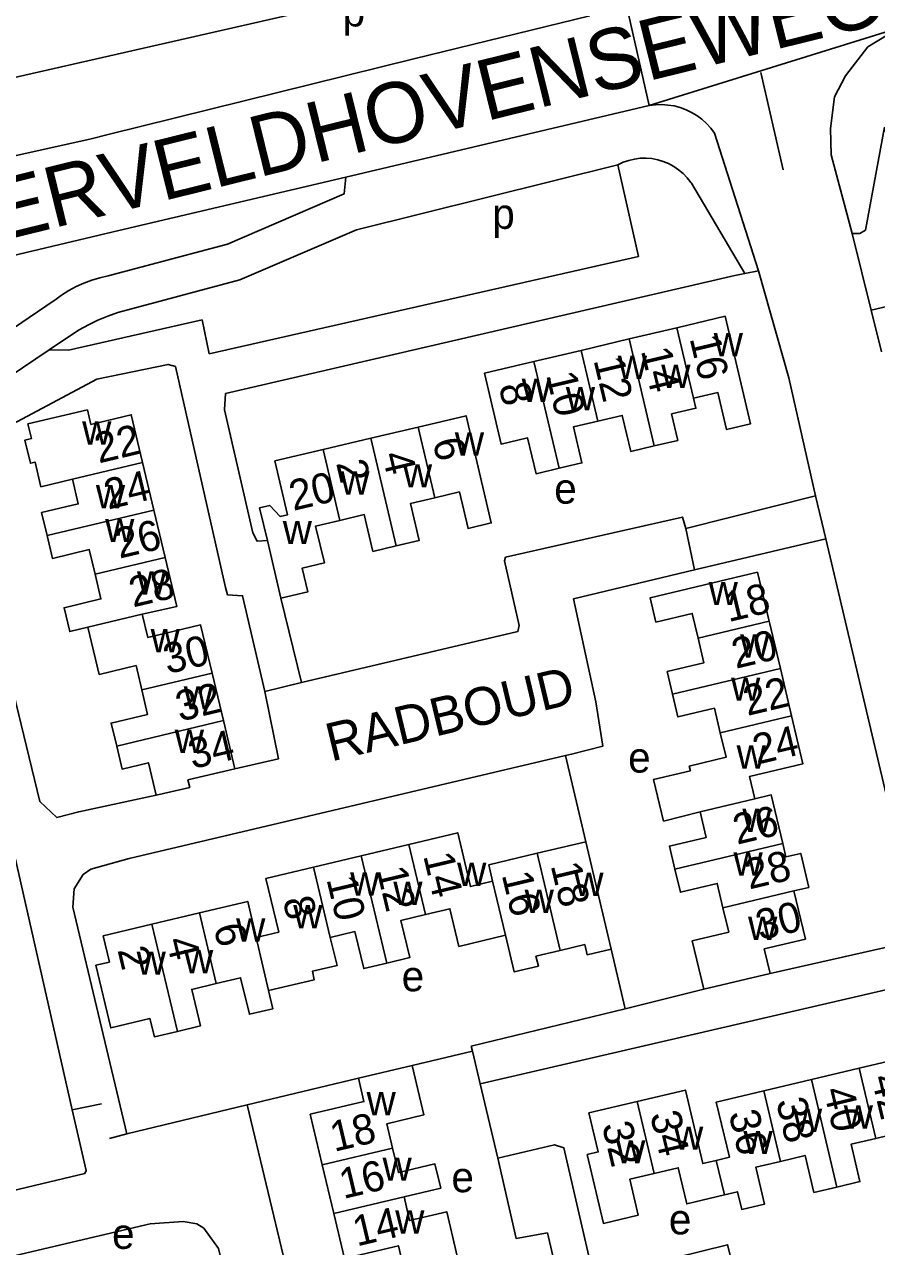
# Model space of a CAD drawing. Extents: x 157646 to 159241, y 379213 to 381217.
# Drawn here: x 158247.5 to 158360.1, y 380777.5 to 380938.8 of the extents above; entities that cross this region are included whole.
import ezdxf

# ---------------------------------------------------------------- set-up
doc = ezdxf.new("R2010")
doc.units = 0
for name, color, linetype in [('BLT_Basislijn', 7, 'Continuous'), ('BLT_Bebouwing', 7, 'Continuous'), ('BLT_Centroide', 7, 'Continuous'), ('BLT_Huisnummer', 7, 'Continuous'), ('BLT_Huisnummer_ tussenligend', 7, 'Continuous'), ('BLT_Onderverdeling_panden', 7, 'Continuous'), ('BLT_Straatnaam', 7, 'Continuous'), ('BLT_Straatnaam_hoofdweg', 7, 'Continuous'), ('BLT_Vlakafsluiter', 7, 'Continuous')]:
    doc.layers.add(name, color=color, linetype=linetype)

msp = doc.modelspace()

# ---------------------------------------------------------------- linework, layer by layer
at = {"layer": 'BLT_Basislijn'}
for p, q in [((158344.76, 380932.48), (158347.72, 380919.64)), ((158330.04, 380928.15), (158289.95, 380918.69)), ((158338.65, 380924.49), (158344.45, 380906.32)), ((158325.89, 380920.33), (158328.62, 380908.21)), ((158289.95, 380918.69), (158259.98, 380911.64)), ((158335.61, 380917.87), (158342.68, 380905.97)), ((158356.85, 380911.26), (158359.36, 380901.14)), ((158328.62, 380908.21), (158271.92, 380895.35)), ((158341.32, 380905.69), (158342.68, 380905.97)), ((158342.68, 380905.97), (158344.45, 380906.32)), ((158238.17, 380893.44), (158251.44, 380902.38)), ((158359.36, 380901.14), (158360.69, 380895.64)), ((158270.97, 380899.83), (158253.35, 380895.83)), ((158271.92, 380895.35), (158270.97, 380899.83)), ((158254.24, 380898.23), (158250.78, 380895.91)), ((158241.22, 380889.46), (158250.78, 380895.91)), ((158253.35, 380895.83), (158250.78, 380895.91)), ((158334.87, 380872.3), (158352, 380876.62)), ((158352, 380876.62), (158353.34, 380870.93)), ((158334.87, 380872.3), (158336.03, 380866.86)), ((158336.03, 380866.86), (158353.34, 380870.93)), ((158353.34, 380870.93), (158365.82, 380818.05)), ((158284.12, 380851.99), (158279.27, 380850.8)), ((158318.96, 380842.32), (158321.67, 380830.96)), ((158365.82, 380818.05), (158346.01, 380813.55)), ((158325.03, 380816.79), (158326.86, 380808.89)), ((158307.72, 380798.98), (158367.08, 380812.75)), ((158306.69, 380803.29), (158298.71, 380801.4)), ((158306.69, 380803.29), (158307.72, 380798.98)), ((158276.95, 380796.21), (158291.62, 380799.72)), ((158307.72, 380798.98), (158310.03, 380789.16)), ((158257.71, 380796.35), (158253.84, 380795.54)), ((158261.04, 380792.41), (158276.95, 380796.21)), ((158258.76, 380791.78), (158261.04, 380792.41)), ((158316.59, 380779.32), (158319.36, 380767.4))]:
    msp.add_line(p, q, dxfattribs=at)
for points in [[(158281.68, 380943.57), (158282.78, 380940.14), (158232.81, 380928.81), (158227.42, 380938.7), (158290.8, 380994.41), (158296.28, 380985.19)], [(158322.18, 380939.98), (158298.93, 380934.3), (158258.59, 380924.33)], [(158363.04, 380938.38), (158358.91, 380935.88), (158355.95, 380932.05), (158354.51, 380929.29), (158353.99, 380925.13), (158354.08, 380921.65), (158356.85, 380911.26)], [(158338.65, 380924.49), (158338.16, 380925.16), (158337.61, 380925.77), (158337, 380926.32), (158336.34, 380926.81), (158335.64, 380927.24), (158334.9, 380927.59), (158334.12, 380927.87), (158333.33, 380928.08), (158332.51, 380928.21), (158331.69, 380928.26), (158330.87, 380928.22), (158330.04, 380928.15)], [(158356.85, 380911.26), (158357.85, 380911.26), (158358.58, 380911.69), (158361.13, 380925.29)], [(158361.13, 380925.29), (158366.65, 380902.84), (158359.36, 380901.14)], [(158229.41, 380918.03), (158244.68, 380921.15), (158256.32, 380923.74), (158258.59, 380924.33)], [(158259.86, 380900.81), (158275.98, 380905.11), (158291.37, 380911.75), (158325.89, 380920.33)], [(158325.89, 380920.33), (158326.59, 380920.65), (158327.32, 380920.9), (158328.08, 380921.08), (158328.84, 380921.17), (158329.62, 380921.19), (158330.39, 380921.13), (158331.15, 380920.99), (158331.89, 380920.77), (158332.6, 380920.47), (158333.28, 380920.1), (158333.92, 380919.67), (158334.51, 380919.17), (158335.05, 380918.61), (158335.52, 380918), (158335.61, 380917.87)], [(158258.57, 380905.65), (158274.33, 380909.85), (158289.76, 380916.5), (158289.95, 380918.69)], [(158232.12, 380903.76), (158240.65, 380907.05), (158259.98, 380911.64)], [(158341.32, 380905.69), (158274.08, 380890.11), (158273.94, 380887.99), (158277.67, 380871.72), (158278.24, 380870.65), (158279.6, 380870.7)], [(158344.45, 380906.32), (158348.46, 380892.19), (158352, 380876.62)], [(158258.57, 380905.65), (158257.48, 380905.41), (158256.4, 380905.1), (158255.36, 380904.71), (158254.34, 380904.25), (158253.36, 380903.71), (158252.42, 380903.11), (158251.52, 380902.44), (158251.44, 380902.38)], [(158259.86, 380900.81), (158258.53, 380900.35), (158257.23, 380899.82), (158255.96, 380899.21), (158254.74, 380898.53), (158254.24, 380898.23)], [(158229.9, 380879.86), (158238.93, 380882.66), (158240.62, 380883.28), (158257.08, 380892.02), (158266.49, 380893.96), (158267.45, 380893.67), (158274.06, 380864.51), (158274.34, 380863.54), (158276.33, 380863.42), (158279.27, 380850.8)], [(158240.4, 380873.84), (158249.53, 380836.28), (158251.78, 380834.15), (158254.68, 380834.9), (158264.9, 380837.08)], [(158284.12, 380851.99), (158312.7, 380858.71), (158312.86, 380859.51), (158310.92, 380868.04), (158311.07, 380868.51), (158334.41, 380873.8), (158334.87, 380872.3)], [(158318.96, 380842.32), (158319.77, 380842.51), (158323.9, 380843.55), (158322.99, 380849.41), (158320.05, 380863.03), (158336.03, 380866.86)], [(158281.4, 380863.12), (158284.12, 380851.99)], [(158279.27, 380850.8), (158281.07, 380841.88), (158275.32, 380840.56)], [(158261.04, 380792.41), (158253.93, 380822.33), (158254.09, 380824.72), (158255.27, 380826.63), (158256.28, 380827.34), (158261.37, 380828.76), (158318.96, 380842.32)], [(158253.84, 380795.54), (158246.19, 380829.22), (158236.45, 380826.81)], [(158326.86, 380808.89), (158327.58, 380809.06), (158337.23, 380811.47)], [(158326.86, 380808.89), (158306.53, 380803.98), (158306.69, 380803.29)], [(158287.22, 380753.19), (158286.95, 380754.31), (158276.95, 380796.21)], [(158222.97, 380779.39), (158223.89, 380779.61), (158255.5, 380787.15), (158255.66, 380787.56), (158253.84, 380795.54)], [(158322.72, 380773.38), (158318.74, 380790.56), (158317.53, 380790.94), (158310.03, 380789.16)], [(158316.59, 380779.32), (158312.44, 380778.59), (158310.03, 380789.16)], [(158235.05, 380773.67), (158264.14, 380780.52), (158268.46, 380780.84), (158270.28, 380780.5), (158271.2, 380779.95), (158273.15, 380777.26), (158281.54, 380741.81)], [(158341.59, 380772.88), (158340.39, 380777.74), (158322.72, 380773.38)]]:
    msp.add_lwpolyline(points, dxfattribs=at)
at = {"layer": 'BLT_Bebouwing'}
for p, q in [((158333.68, 380898.81), (158327.37, 380897.32)), ((158327.37, 380897.32), (158321.04, 380895.82)), ((158321.04, 380895.82), (158314.79, 380894.34)), ((158299.53, 380885.7), (158293.25, 380884.22)), ((158293.25, 380884.22), (158286.98, 380882.73)), ((158264.61, 380874.73), (158263.12, 380881)), ((158266.1, 380868.46), (158264.61, 380874.73)), ((158345.87, 380860.06), (158347.36, 380853.81)), ((158273.8, 380846.94), (158272.31, 380853.2)), ((158347.36, 380853.81), (158348.84, 380847.57)), ((158275.32, 380840.56), (158273.8, 380846.94)), ((158298.27, 380830.59), (158292, 380829.1)), ((158321.67, 380830.96), (158315.24, 380829.43)), ((158325.03, 380816.79), (158321.67, 380830.96)), ((158292, 380829.1), (158285.7, 380827.61)), ((158270.62, 380821.55), (158264.36, 380820.06)), ((158346.01, 380813.55), (158337.23, 380811.47)), ((158298.71, 380801.4), (158291.62, 380799.72)), ((158357.77, 380801.05), (158351.47, 380799.55)), ((158351.47, 380799.55), (158345.17, 380798.06)), ((158286.85, 380788.3), (158288.38, 380781.86))]:
    msp.add_line(p, q, dxfattribs=at)
for points in [[(158335.89, 380889.49), (158339.1, 380890.25), (158340.26, 380885.36), (158343.41, 380886.11), (158340.05, 380900.32), (158333.68, 380898.81)], [(158314.79, 380894.34), (158308.27, 380892.8), (158310.48, 380883.44), (158313.97, 380884.26), (158315.09, 380879.53), (158318.12, 380880.25)], [(158263.12, 380881), (158261.62, 380887.31), (158256.3, 380886.04), (158255.84, 380887.95), (158247.97, 380886.12), (158248.43, 380884.17), (158247.58, 380883.97), (158248.3, 380880.91), (158248.92, 380881.06), (158249.69, 380877.81), (158253.85, 380878.8)], [(158330.7, 380883.2), (158333.8, 380883.93), (158332.98, 380887.42), (158336.2, 380888.18), (158335.89, 380889.49)], [(158301.74, 380876.37), (158304.96, 380877.13), (158306.11, 380872.3), (158309.18, 380873.03), (158305.84, 380887.19), (158299.53, 380885.7)], [(158318.12, 380880.25), (158321.15, 380880.96), (158320.03, 380885.71), (158323.25, 380886.47)], [(158323.25, 380886.47), (158326.48, 380887.23), (158327.6, 380882.47), (158330.7, 380883.2)], [(158286.98, 380882.73), (158280.59, 380881.22), (158282.27, 380874.12), (158281.29, 380873.89), (158279.92, 380875.35), (158278.57, 380875.04)], [(158253.85, 380878.8), (158254.62, 380875.55), (158249.79, 380874.4), (158250.5, 380871.38)], [(158278.57, 380875.04), (158279.6, 380870.7)], [(158296.61, 380870), (158299.67, 380870.73), (158298.51, 380875.61), (158301.74, 380876.37)], [(158289.19, 380873.38), (158292.4, 380874.14), (158293.55, 380869.28), (158296.61, 380870)], [(158281.4, 380863.12), (158284.95, 380863.96), (158284.21, 380867.07), (158287.13, 380867.76), (158285.98, 380872.62), (158289.19, 380873.38)], [(158250.5, 380871.38), (158251.22, 380868.36), (158256.08, 380869.51), (158256.85, 380866.26)], [(158279.6, 380870.7), (158281.4, 380863.12)], [(158263.07, 380860.98), (158267.64, 380861.99), (158266.1, 380868.46)], [(158256.85, 380866.26), (158257.62, 380863), (158252.75, 380861.84), (158253.5, 380858.7), (158255.91, 380859.28)], [(158336.48, 380857.83), (158335.71, 380861.09), (158330.92, 380859.95), (158330.16, 380863.17), (158344.33, 380866.53), (158345.87, 380860.06)], [(158272.31, 380853.2), (158270.79, 380859.58), (158263.8, 380857.92), (158263.07, 380860.98)], [(158255.91, 380859.28), (158257.39, 380853.05), (158262.26, 380854.2), (158263.03, 380850.99)], [(158333.12, 380850.42), (158332.41, 380853.42), (158337.25, 380854.57), (158336.48, 380857.83)], [(158263.03, 380850.99), (158263.79, 380847.77), (158258.97, 380846.62), (158259.7, 380843.59)], [(158339.42, 380845.34), (158338.65, 380848.57), (158333.83, 380847.42), (158333.12, 380850.42)], [(158348.84, 380847.57), (158350.34, 380841.25), (158343.28, 380839.57), (158343.98, 380836.63)], [(158336.76, 380834.92), (158331.93, 380833.68), (158330.62, 380839.18), (158335.48, 380840.33), (158335.33, 380840.95), (158340.19, 380842.1), (158339.42, 380845.34)], [(158259.7, 380843.59), (158260.42, 380840.55), (158263.89, 380841.38), (158264.9, 380837.08)], [(158264.9, 380837.08), (158269.35, 380838.13), (158269.11, 380839.14), (158275.32, 380840.56)], [(158343.98, 380836.63), (158346.14, 380837.14), (158347.66, 380830.72)], [(158333.43, 380827.34), (158332.71, 380830.38), (158337.57, 380831.53), (158336.76, 380834.92)], [(158309.35, 380825.74), (158306.43, 380825.04), (158304.74, 380832.13), (158298.27, 380830.59)], [(158347.66, 380830.72), (158348.08, 380828.95), (158350.05, 380829.42), (158351.11, 380824.93), (158349.15, 380824.47)], [(158315.24, 380829.43), (158308.86, 380827.91), (158309.35, 380825.74)], [(158285.7, 380827.61), (158279.42, 380826.11), (158281.1, 380819.02), (158278.12, 380818.31)], [(158339.77, 380822.24), (158339.01, 380825.45), (158334.15, 380824.29), (158333.43, 380827.34)], [(158349.15, 380824.47), (158350.66, 380818.1), (158345.23, 380816.8), (158346.01, 380813.55)], [(158278.12, 380818.31), (158277.01, 380823.07), (158270.62, 380821.55)], [(158300.47, 380821.33), (158303.71, 380822.1), (158304.89, 380817.14), (158311.05, 380818.6)], [(158337.23, 380811.47), (158335.71, 380817.88), (158340.54, 380819.03), (158339.77, 380822.24)], [(158295.37, 380814.93), (158298.41, 380815.65), (158297.24, 380820.56), (158300.47, 380821.33)], [(158264.36, 380820.06), (158257.93, 380818.53), (158258.75, 380815.07), (158256.95, 380814.64), (158258.91, 380806.38), (158264.1, 380807.61), (158264.68, 380805.2), (158267.72, 380805.92)], [(158287.91, 380818.33), (158291.16, 380819.1), (158292.33, 380814.21), (158295.37, 380814.93)], [(158311.05, 380818.6), (158312.2, 380813.76), (158315.39, 380814.52), (158315.08, 380815.84), (158318.29, 380816.6)], [(158279.76, 380811.3), (158285.8, 380812.74), (158285.56, 380813.85), (158288.8, 380814.6), (158287.91, 380818.33)], [(158318.29, 380816.6), (158321.51, 380817.37), (158321.82, 380816.03), (158325.03, 380816.79)], [(158267.72, 380805.92), (158270.75, 380806.64), (158269.61, 380811.46), (158272.84, 380812.23)], [(158272.84, 380812.23), (158276.07, 380813), (158277.22, 380808.17), (158280.33, 380808.91), (158279.76, 380811.3)], [(158359.96, 380791.78), (158363.22, 380792.55), (158364.36, 380787.73), (158367.46, 380788.46), (158364.12, 380802.55), (158357.77, 380801.05)], [(158296.14, 380790.51), (158295.38, 380793.73), (158300.25, 380794.88), (158298.71, 380801.4)], [(158291.62, 380799.72), (158292.35, 380796.64), (158285.27, 380794.97), (158286.85, 380788.3)], [(158338.88, 380788.88), (158337.11, 380788.46), (158334.81, 380798.16), (158328.45, 380796.65)], [(158345.17, 380798.06), (158338.89, 380796.58), (158340.62, 380789.29), (158338.88, 380788.88)], [(158328.45, 380796.65), (158322.08, 380795.15), (158323.3, 380790.01), (158321.84, 380789.66), (158323.99, 380780.57), (158328.59, 380781.66), (158327.47, 380786.4), (158330.69, 380787.16)], [(158354.83, 380785.37), (158357.87, 380786.09), (158356.7, 380791.01), (158359.96, 380791.78)], [(158297.65, 380784.06), (158302.49, 380785.2), (158301.73, 380788.42), (158296.91, 380787.28), (158296.14, 380790.51)], [(158347.37, 380788.76), (158350.63, 380789.54), (158351.79, 380784.65), (158354.83, 380785.37)], [(158330.69, 380787.16), (158333.87, 380787.91), (158334.99, 380783.15), (158339.98, 380784.33)], [(158339.98, 380784.33), (158341.69, 380784.74), (158342.25, 380782.41), (158345.26, 380783.12), (158344.11, 380787.99), (158347.37, 380788.76)], [(158304.72, 380776.07), (158303.3, 380782.1), (158298.39, 380780.93), (158297.65, 380784.06)], [(158288.38, 380781.86), (158289.78, 380775.93), (158296.9, 380777.62), (158297.66, 380774.4)]]:
    msp.add_lwpolyline(points, dxfattribs=at)
at = {"layer": 'BLT_Onderverdeling_panden'}
for p, q in [((158335.89, 380889.49), (158333.68, 380898.81)), ((158330.7, 380883.2), (158327.37, 380897.32)), ((158323.25, 380886.47), (158321.04, 380895.82)), ((158318.12, 380880.25), (158314.79, 380894.34)), ((158301.74, 380876.37), (158299.53, 380885.7)), ((158296.61, 380870), (158293.25, 380884.22)), ((158289.19, 380873.38), (158286.98, 380882.73)), ((158253.85, 380878.8), (158263.12, 380881)), ((158250.5, 380871.38), (158264.61, 380874.73)), ((158256.85, 380866.26), (158266.1, 380868.46)), ((158255.91, 380859.28), (158263.07, 380860.98)), ((158336.48, 380857.83), (158345.87, 380860.06)), ((158263.03, 380850.99), (158272.31, 380853.2)), ((158333.12, 380850.42), (158347.36, 380853.81)), ((158339.42, 380845.34), (158348.84, 380847.57)), ((158259.7, 380843.59), (158273.8, 380846.94)), ((158336.76, 380834.92), (158343.98, 380836.63)), ((158300.47, 380821.33), (158298.27, 380830.59)), ((158333.43, 380827.34), (158347.66, 380830.72)), ((158295.37, 380814.93), (158292, 380829.1)), ((158318.29, 380816.6), (158315.24, 380829.43)), ((158287.91, 380818.33), (158285.7, 380827.61)), ((158309.35, 380825.74), (158311.05, 380818.6)), ((158339.77, 380822.24), (158349.15, 380824.47)), ((158272.84, 380812.23), (158270.62, 380821.55)), ((158267.72, 380805.92), (158264.36, 380820.06)), ((158278.12, 380818.31), (158279.76, 380811.3)), ((158359.96, 380791.78), (158357.77, 380801.05)), ((158354.83, 380785.37), (158351.47, 380799.55)), ((158347.37, 380788.76), (158345.17, 380798.06)), ((158328.45, 380796.65), (158330.69, 380787.16)), ((158296.14, 380790.51), (158286.85, 380788.3)), ((158338.88, 380788.88), (158339.98, 380784.33)), ((158297.65, 380784.06), (158288.38, 380781.86))]:
    msp.add_line(p, q, dxfattribs=at)
at = {"layer": 'BLT_Vlakafsluiter'}
for p, q in [((158327.08, 380941.17), (158330.04, 380928.15)), ((158330.04, 380928.15), (158363.04, 380938.38))]:
    msp.add_line(p, q, dxfattribs=at)

# ---------------------------------------------------------------- texts
at = {"layer": 'BLT_Centroide'}
for s, p in [('p', (158289.54, 380938.58)), ('p', (158309.3, 380911.86)), ('w', (158338.55, 380895.05)), ('w', (158325.88, 380892.03)), ('w', (158331.62, 380890.86)), ('w', (158313.19, 380889.02)), ('w', (158319.02, 380887.91)), ('w', (158255.14, 380883.38)), ('w', (158304.36, 380881.92)), ('w', (158289.23, 380876.78)), ('w', (158297.5, 380877.72)), ('e', (158317.49, 380875.58)), ('w', (158256.95, 380874.98)), ('w', (158258.17, 380870.5)), ('w', (158281.63, 380870.24)), ('w', (158262.38, 380863.59)), ('w', (158337.88, 380862.19)), ('w', (158264.18, 380855.97)), ('w', (158342.05, 380855.25)), ('w', (158340.84, 380849.56)), ('w', (158268.55, 380848.41)), ('w', (158267.37, 380842.66)), ('e', (158327.25, 380840.08)), ('w', (158341.57, 380840.62)), ('w', (158342.34, 380832.25)), ('w', (158341.16, 380826.47)), ('w', (158290.53, 380823.84)), ('w', (158304.66, 380825.11)), ('w', (158320.14, 380823.81)), ('w', (158296.23, 380822.61)), ('w', (158313.58, 380821.56)), ('w', (158283.02, 380819.52)), ('w', (158275.47, 380817.77)), ('w', (158343.09, 380817.97)), ('w', (158262.33, 380813.39)), ('w', (158268.59, 380813.59)), ('e', (158297.34, 380811.21)), ('w', (158292.7, 380794.84)), ('w', (158355.72, 380793.08)), ('w', (158349.01, 380792.63)), ('w', (158333.31, 380790.28)), ('w', (158342.47, 380789.71)), ('w', (158325.66, 380788.48)), ('w', (158294.81, 380786.19)), ('e', (158303.91, 380784.68)), ('w', (158296.48, 380779.22)), ('e', (158332.63, 380779.12)), ('e', (158259.09, 380777.2))]:
    msp.add_text(s, height=4, dxfattribs=at).set_placement(p)
at = {"layer": 'BLT_Huisnummer'}
for s, rotation, p in [('16', 283.2971, (158335.35, 380897.42)), ('12', 283.2971, (158322.66, 380894.54)), ('8', 283.2971, (158310.14, 380891.13)), ('22', 13.3791, (158257.33, 380880.88)), ('6', 283.3016, (158301.4, 380883.84)), ('20', 13.3138, (158283.02, 380874.62)), ('28', 13.3791, (158261.86, 380861.87)), ('18', 13.3657, (158340.49, 380859.93)), ('30', 13.3791, (158266.4, 380853.07)), ('24', 13.3657, (158344.23, 380841.1)), ('34', 13.3791, (158269.71, 380840.53)), ('26', 13.3657, (158341.63, 380830.55)), ('14', 283.3626, (158300.17, 380829.11)), ('18', 283.3626, (158317, 380827.83)), ('8', 283.3626, (158281.61, 380823.29)), ('30', 13.3657, (158344.65, 380817.92)), ('6', 283.3626, (158272.48, 380819.72)), ('2', 283.3626, (158259.79, 380816.68)), ('42', 283.33, (158359.35, 380799.81)), ('18', 13.318, (158288.42, 380790)), ('34', 283.322, (158330.12, 380794.96)), ('36', 283.3214, (158340.51, 380795.1)), ('32', 283.3226, (158323.77, 380793.56)), ('14', 13.3196, (158291.42, 380777.51))]:
    msp.add_text(s, height=4, rotation=rotation, dxfattribs=at).set_placement(p)
at = {"layer": 'BLT_Huisnummer_ tussenligend'}
for s, rotation, p in [('14', 283.2971, (158328.92, 380895.8)), ('10', 283.2971, (158316.4, 380892.59)), ('4', 283.2989, (158294.74, 380882.04)), ('24', 13.3791, (158258.57, 380874.79)), ('2', 283.2989, (158288.66, 380880.95)), ('26', 13.3791, (158260.06, 380868.31)), ('20', 13.3657, (158341.46, 380853.77)), ('22', 13.3657, (158342.99, 380847.55)), ('32', 13.3791, (158268.03, 380846.8)), ('28', 13.3657, (158343.25, 380824.64)), ('12', 283.3626, (158294.01, 380827.25)), ('16', 283.3626, (158310.54, 380826.6)), ('10', 283.3626, (158287.39, 380826.01)), ('4', 283.3626, (158266.22, 380817.95)), ('40', 283.3214, (158353.03, 380798.15)), ('38', 283.3214, (158346.77, 380796.71)), ('16', 13.3196, (158289.64, 380783.78))]:
    msp.add_text(s, height=4, rotation=rotation, dxfattribs=at).set_placement(p)
at = {"layer": 'BLT_Straatnaam'}
msp.add_text('RADBOUD', height=5, rotation=13.4345, dxfattribs=at).set_placement((158288.02, 380841.53))
at = {"layer": 'BLT_Straatnaam_hoofdweg'}
msp.add_text('MEERVELDHOVENSEWEG', height=8, rotation=13.8813, dxfattribs=at).set_placement((158228.8, 380906.37))

doc.saveas('drawing.dxf')
